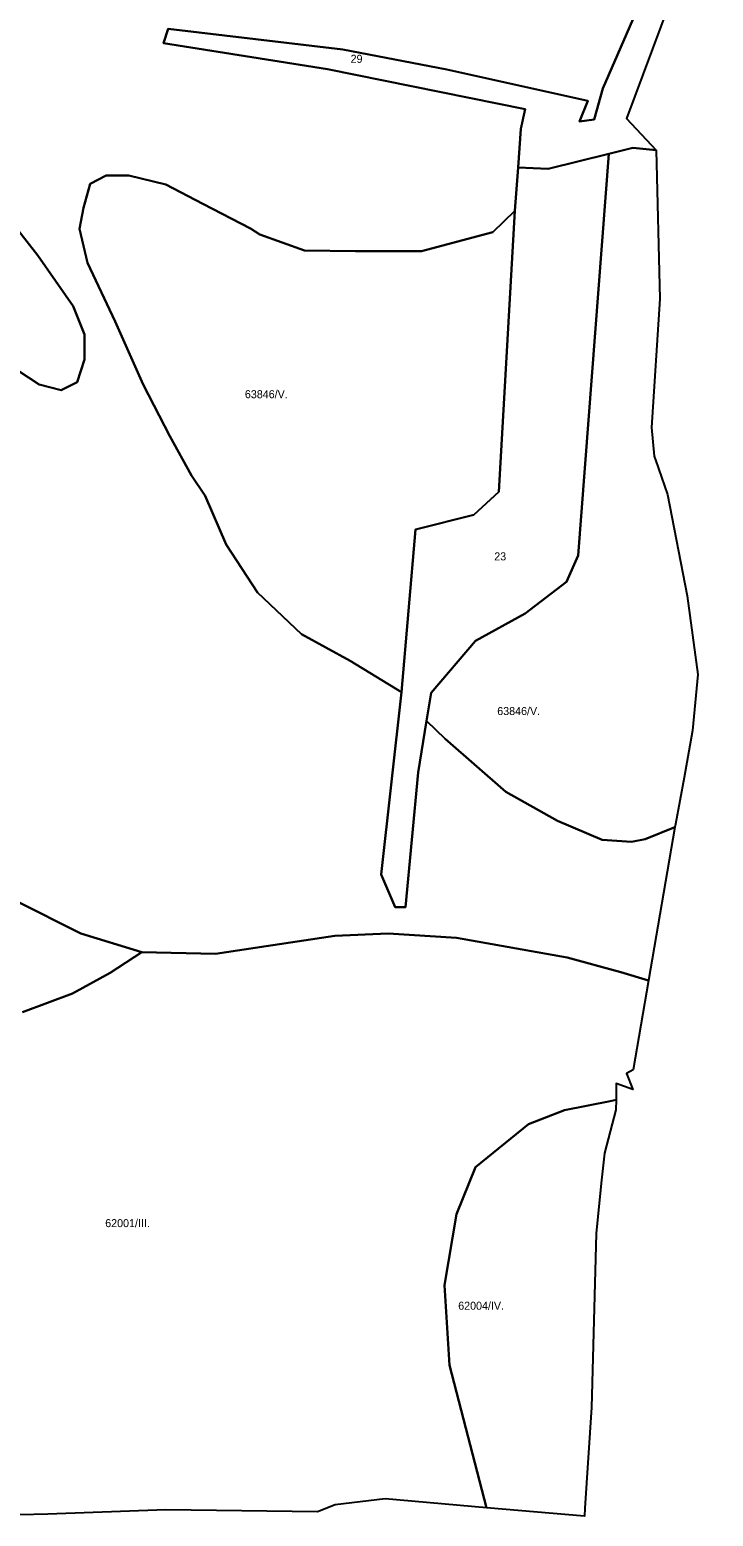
# Model space of a CAD drawing. Extents: x -521621 to -516761, y -1190184 to -1184927.
# Drawn here: x -518423 to -518082, y -1190184 to -1189440 of the extents above; entities that cross this region are included whole.
import ezdxf

# ---------------------------------------------------------------- set-up
doc = ezdxf.new("R2010")
doc.units = 0
doc.layers.add('BPEJ_s', color=7, linetype='Continuous')

msp = doc.modelspace()

# ---------------------------------------------------------------- linework, layer by layer
at = {"layer": 'BPEJ_s'}
for p, q in [((-518179.21, -1189509.35), (-518180.83, -1189531.03)), ((-518100.9, -1189839.17), (-518114.11, -1189915.83))]:
    msp.add_line(p, q, dxfattribs=at)
for points in [[(-518179.21, -1189509.35), (-518177.97, -1189490.02), (-518175.78, -1189480.15), (-518274.52, -1189460.18), (-518356.45, -1189447.17), (-518354.11, -1189440.01), (-518266.87, -1189450.34), (-518214.9, -1189460.28), (-518144.38, -1189476), (-518148.62, -1189486.34), (-518141.3, -1189485.42), (-518136.87, -1189469.83), (-518107.05, -1189401.19), (-518094.78, -1189367.28), (-518081.72, -1189339.3), (-518089.17, -1189386.88), (-518094.18, -1189404.37), (-518103.69, -1189427.69), (-518125.04, -1189484.87), (-518110.32, -1189500.73), (-518121.9, -1189499.52), (-518133.91, -1189502.5), (-518164.27, -1189510.04)], [(-518237.55, -1189771.67), (-518230.45, -1189690.28), (-518201.42, -1189682.93), (-518188.92, -1189671.53), (-518180.83, -1189531.03), (-518179.21, -1189509.35), (-518164.27, -1189510.04), (-518133.91, -1189502.5), (-518149.17, -1189703.28), (-518155.05, -1189716.52), (-518175.64, -1189732.34), (-518200.59, -1189745.88), (-518222.64, -1189772), (-518224.97, -1189785.97), (-518229.26, -1189811.72), (-518235.51, -1189879.03), (-518240.65, -1189879.03), (-518247.64, -1189862.84)], [(-518224.97, -1189785.97), (-518222.64, -1189772), (-518200.59, -1189745.88), (-518175.64, -1189732.34), (-518155.05, -1189716.52), (-518149.17, -1189703.28), (-518133.91, -1189502.5), (-518121.9, -1189499.52), (-518110.32, -1189500.73), (-518108.38, -1189574.91), (-518112.58, -1189639.23), (-518111.93, -1189646.44), (-518111.29, -1189653.64), (-518110.97, -1189654.57), (-518110.64, -1189655.5), (-518104.65, -1189672.73), (-518094.79, -1189723.47), (-518089.45, -1189762.85), (-518092.04, -1189790.82), (-518096.33, -1189814.2), (-518100.62, -1189837.57), (-518100.9, -1189839.17), (-518115.72, -1189845.18), (-518122.65, -1189846.5), (-518137.16, -1189845.51), (-518159.6, -1189835.94), (-518185.34, -1189821.41), (-518215.69, -1189795)], [(-518237.55, -1189771.67), (-518263.18, -1189755.95), (-518287.49, -1189742.65), (-518309.51, -1189721.75), (-518325.07, -1189697.82), (-518335.71, -1189673.5), (-518342.4, -1189663.38), (-518353.28, -1189643.63), (-518366.57, -1189617.83), (-518380.68, -1189586.38), (-518394.37, -1189556.95), (-518398.4, -1189540.02), (-518396.39, -1189529.54), (-518393.17, -1189517.44), (-518385.11, -1189513.41), (-518373.83, -1189513.41), (-518355.29, -1189517.84), (-518336.76, -1189527.52), (-518312.92, -1189539.77), (-518308.37, -1189542.81), (-518285.97, -1189550.79), (-518260.53, -1189551.17), (-518227.49, -1189551.17), (-518191.8, -1189541.67), (-518180.83, -1189531.03), (-518188.92, -1189671.53), (-518201.42, -1189682.93), (-518230.45, -1189690.28)], [(-518195.08, -1190179.29), (-518213.5, -1190108), (-518216, -1190068), (-518210, -1190032.5), (-518200.5, -1190009), (-518174, -1189987.5), (-518156, -1189980.5), (-518133.18, -1189976.02), (-518130.31, -1189975.46), (-518130.37, -1189980.35), (-518136.02, -1190002.06), (-518137.8, -1190017.12), (-518140.23, -1190042.21), (-518142.65, -1190129.19), (-518145.89, -1190179.61), (-518146.15, -1190183.59)]]:
    msp.add_lwpolyline(points, close=True, dxfattribs=at)
for points in [[(-518081.72, -1189339.3), (-518094.78, -1189367.28), (-518107.05, -1189401.19), (-518136.87, -1189469.83), (-518141.3, -1189485.42), (-518148.62, -1189486.34), (-518144.38, -1189476), (-518214.9, -1189460.28), (-518266.87, -1189450.34), (-518354.11, -1189440.01), (-518356.45, -1189447.17), (-518274.52, -1189460.18), (-518175.78, -1189480.15), (-518177.97, -1189490.02), (-518179.21, -1189509.35)], [(-518180.83, -1189531.03), (-518191.8, -1189541.67), (-518227.49, -1189551.17), (-518260.53, -1189551.17), (-518285.97, -1189550.79), (-518308.37, -1189542.81), (-518312.92, -1189539.77), (-518336.76, -1189527.52), (-518355.29, -1189517.84), (-518373.83, -1189513.41), (-518385.11, -1189513.41), (-518393.17, -1189517.44), (-518396.39, -1189529.54), (-518398.4, -1189540.02), (-518394.37, -1189556.95), (-518380.68, -1189586.38), (-518366.57, -1189617.83), (-518353.28, -1189643.63), (-518342.4, -1189663.38), (-518335.71, -1189673.5), (-518325.07, -1189697.82), (-518309.51, -1189721.75), (-518287.49, -1189742.65), (-518263.18, -1189755.95), (-518237.55, -1189771.67)], [(-518441.51, -1189525.1), (-518419.35, -1189553.32), (-518401.63, -1189578.72), (-518395.99, -1189592.83), (-518395.99, -1189605.33), (-518399.61, -1189616.62), (-518407.67, -1189620.65), (-518418.55, -1189617.83), (-518435.07, -1189606.94)], [(-518435.07, -1189606.94), (-518418.55, -1189617.83), (-518407.67, -1189620.65), (-518399.61, -1189616.62), (-518395.99, -1189605.33), (-518395.99, -1189592.83), (-518401.63, -1189578.72), (-518419.35, -1189553.32), (-518441.51, -1189525.1)], [(-518237.55, -1189771.67), (-518247.64, -1189862.84), (-518240.65, -1189879.03), (-518235.51, -1189879.03), (-518229.26, -1189811.72), (-518224.97, -1189785.97)], [(-518224.97, -1189785.97), (-518215.69, -1189795), (-518185.34, -1189821.41), (-518159.6, -1189835.94), (-518137.16, -1189845.51), (-518122.65, -1189846.5), (-518115.72, -1189845.18), (-518100.9, -1189839.17)], [(-518430.3, -1189875.88), (-518397.71, -1189892.18), (-518367.27, -1189901.62), (-518383.14, -1189911.91), (-518402, -1189922.21), (-518426.87, -1189931.65)], [(-518367.27, -1189901.62), (-518397.71, -1189892.18), (-518430.3, -1189875.88)], [(-518426.87, -1189931.65), (-518402, -1189922.21), (-518383.14, -1189911.91), (-518367.27, -1189901.62), (-518330.4, -1189902.48), (-518305.1, -1189898.61), (-518270.8, -1189893.47), (-518244.22, -1189892.18), (-518210.08, -1189894.38), (-518154.65, -1189904.28), (-518127.93, -1189911.54), (-518114.11, -1189915.83), (-518121.8, -1189960.44), (-518125.03, -1189962.22), (-518121.96, -1189970.31), (-518130.21, -1189967.24), (-518130.31, -1189975.46), (-518133.18, -1189976.02), (-518156, -1189980.5), (-518174, -1189987.5), (-518200.5, -1190009), (-518210, -1190032.5), (-518216, -1190068), (-518213.5, -1190108), (-518195.08, -1190179.29), (-518245.69, -1190174.85), (-518270.64, -1190177.79), (-518279.52, -1190181.35), (-518355.34, -1190180.4), (-518414.24, -1190182.61), (-518442.72, -1190183.21)], [(-518114.11, -1189915.83), (-518127.93, -1189911.54), (-518154.65, -1189904.28), (-518210.08, -1189894.38), (-518244.22, -1189892.18), (-518270.8, -1189893.47), (-518305.1, -1189898.61), (-518330.4, -1189902.48), (-518367.27, -1189901.62)]]:
    msp.add_lwpolyline(points, dxfattribs=at)

# ---------------------------------------------------------------- texts
for s, p in [('29', (-518262.96, -1189456.99)), ('63846/V.', (-518315.79, -1189624.67)), ('23', (-518191.17, -1189705.74)), ('63846/V.', (-518189.67, -1189783.06)), ('62001/III.', (-518385.6, -1190039.05)), ('62004/IV.', (-518209.19, -1190080.34))]:
    msp.add_text(s, height=4, dxfattribs=at).set_placement(p)

doc.saveas('drawing.dxf')
